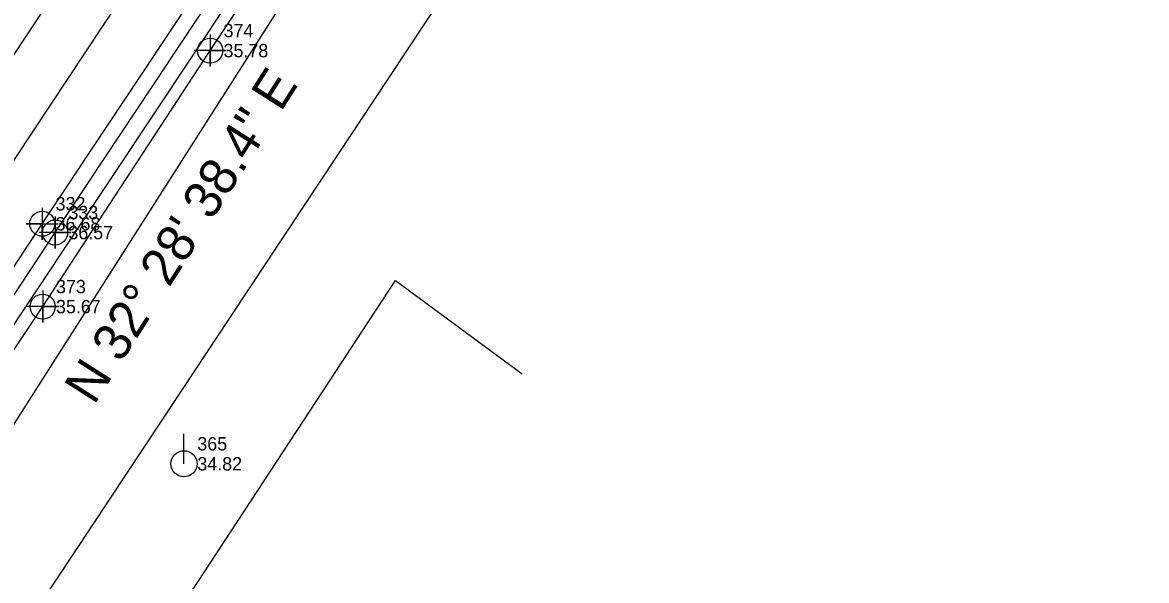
# Model space of a CAD drawing. Extents: x 2603627 to 2605187, y 896619 to 899063.
# Drawn here: x 2604872.4 to 2605082.8, y 898575.9 to 898680.4 of the extents above; entities that cross this region are included whole.
import ezdxf

# ---------------------------------------------------------------- set-up
doc = ezdxf.new("R2010")
doc.units = 0
for name, color, linetype in [('Exist Horizontal Alignment', 7, 'Continuous'), ('Exist Horizontal Baseline Alignment', 7, 'Continuous'), ('Exist Horizontal Baseline Alignment Direction Label', 7, 'Continuous'), ('Exist Right of Way Line', 7, 'Continuous'), ('Exist Roads EOP', 7, 'Continuous'), ('Exist Roads EOP Cogo Elevation', 7, 'Continuous'), ('Exist Roads EOP Cogo Number', 7, 'Continuous'), ('Exist Roads EOP Cogo Point CELL', 7, 'Continuous'), ('Exist Roads EOT', 7, 'Continuous'), ('Exist Roads EOT Cogo Elevation', 7, 'Continuous'), ('Exist Roads EOT Cogo Number', 7, 'Continuous'), ('Exist Roads EOT Cogo Point CELL', 7, 'Continuous'), ('Exist Utilities Power Pole CELL', 7, 'Continuous'), ('Exist Utilities Power Pole Cogo Elevation', 7, 'Continuous'), ('Exist Utilities Power Pole Cogo Number', 7, 'Continuous'), ('Exist Utilities Telephone UG Cable SUE LOS C', 7, 'Continuous'), ('Exist Utilities Water UG Line SUE LOS B', 7, 'Continuous'), ('Exist Utilities Water UG Line SUE LOS B Cogo Elevation', 7, 'Continuous'), ('Exist Utilities Water UG Line SUE LOS B Cogo Number', 7, 'Continuous'), ('Exist Utilities Water UG Line SUE LOS B Cogo Point CELL', 7, 'Continuous'), ('Exist Vegetation Woods Line', 7, 'Continuous')]:
    doc.layers.add(name, color=color, linetype=linetype)

# ---------------------------------------------------------------- blocks, each defined once
blk = doc.blocks.new('EXIST ROADS EOT COGO POINT')
at = {"layer": 'Exist Roads EOT Cogo Point CELL'}
blk.add_lwpolyline([(0, 0.06), (0, -0.06), (0, 0), (-0.06, 0), (0.06, 0)], dxfattribs=at)
blk.add_circle((0, 0), 0.0469, dxfattribs=at)
blk = doc.blocks.new('EXIST ROADS EOP COGO POINT')
at = {"layer": 'Exist Roads EOP Cogo Point CELL'}
blk.add_lwpolyline([(0, 0.06), (0, -0.06), (0, 0), (0.06, 0), (-0.06, 0)], dxfattribs=at)
blk.add_circle((0, 0), 0.0469, dxfattribs=at)
blk = doc.blocks.new('EXIST UTILITIES WATER UG LINE SUE LOS B COGO POINT')
at = {"layer": 'Exist Utilities Water UG Line SUE LOS B Cogo Point CELL'}
blk.add_lwpolyline([(0, 0.06), (0, -0.06), (0, 0), (0.06, 0), (-0.06, 0)], dxfattribs=at)
blk.add_circle((0, 0), 0.0469, dxfattribs=at)

msp = doc.modelspace()

# ---------------------------------------------------------------- linework, layer by layer
at = {"layer": 'Exist Horizontal Alignment'}
msp.add_line((2604681.44, 898368.79), (2605041.11, 898911.74), dxfattribs=at)
at = {"layer": 'Exist Horizontal Baseline Alignment'}
msp.add_line((2604793.6, 898483.9), (2605028.26, 898852.56), dxfattribs=at)
at = {"layer": 'Exist Right of Way Line'}
msp.add_line((2604723.13, 898341.18), (2605082.79, 898884.13), dxfattribs=at)
at = {"layer": 'Exist Roads EOP'}
msp.add_lwpolyline([(2604713.86, 898392.44), (2604740.28, 898432.25), (2604768.45, 898474.26), (2604797.27, 898517.92), (2604823.93, 898558.47), (2604851.31, 898599.84), (2604878.52, 898641.09), (2604906.84, 898683.65), (2604934.68, 898725.71), (2604962.63, 898767.92), (2604989.32, 898808.49), (2605016.42, 898849.59), (2605045.34, 898893.33), (2605052.55, 898904.16)], dxfattribs=at)
at = {"layer": 'Exist Roads EOT'}
for points in [[(2604580.65, 898235.67), (2604609.23, 898279.3), (2604636.66, 898320.72), (2604665.18, 898363.91), (2604693.37, 898406.36), (2604719.95, 898446.05), (2604748, 898488.34), (2604776.15, 898530.84), (2604803.5, 898572.3), (2604830.95, 898613.91), (2604857.58, 898654.47), (2604886.02, 898697.38), (2604913.86, 898739.33), (2604942.03, 898781.72), (2604969.06, 898822.38), (2604996.07, 898863.44), (2605024.73, 898906.73), (2605032, 898917.78)], [(2604598.04, 898223.4), (2604627.23, 898267.23), (2604654.64, 898308.57), (2604683.28, 898352.01), (2604711.27, 898394.14), (2604737.98, 898434.05), (2604766.04, 898475.94), (2604794.96, 898519.26), (2604821.61, 898559.82), (2604848.89, 898601.4), (2604876.12, 898642.73), (2604904.4, 898685.35), (2604932.33, 898727.23), (2604960.29, 898769.49), (2604987.32, 898810.19), (2605014.12, 898850.95), (2605043.08, 898894.89), (2605050.2, 898905.72)]]:
    msp.add_lwpolyline(points, dxfattribs=at)
at = {"layer": 'Exist Utilities Power Pole CELL'}
for q in [(2604902.65, 898603.41), (2604902.65, 898597.79)]:
    msp.add_line((2604902.65, 898597.79), q, dxfattribs=at)
msp.add_circle((2604902.65, 898597.79), 2.45, dxfattribs=at)
at = {"layer": 'Exist Utilities Telephone UG Cable SUE LOS C'}
msp.add_line((2604850.74, 898593.69), (2605031.63, 898865.69), dxfattribs=at)
at = {"layer": 'Exist Utilities Water UG Line SUE LOS B'}
msp.add_lwpolyline([(2604590.41, 898183.07), (2604608.13, 898210.78), (2604631.33, 898247.72), (2604631.98, 898248.77), (2604637.93, 898260.9), (2604650.01, 898281.75), (2604670.13, 898312.66), (2604706.14, 898370.49), (2604744.2, 898428.79), (2604775.85, 898478.14), (2604817.62, 898541.22), (2604844.76, 898580.18), (2604876.2, 898627.22), (2604907.55, 898675.15), (2604931.69, 898711.47), (2604963.51, 898758.63), (2604991.08, 898800.9), (2605022.23, 898847.26), (2605044.13, 898880.13), (2605057.71, 898900.74)], dxfattribs=at)
at = {"layer": 'Exist Vegetation Woods Line'}
msp.add_lwpolyline([(2604864.62, 898513.8), (2604942.25, 898632.13), (2604965.96, 898614.62)], dxfattribs=at)

# ---------------------------------------------------------------- block references
at = {"layer": 'Exist Roads EOP Cogo Point CELL', "xscale": 50, "yscale": 50}
msp.add_blockref('EXIST ROADS EOP COGO POINT', (2604878.52, 898641.09), dxfattribs=at)
at = {"layer": 'Exist Roads EOT Cogo Point CELL', "xscale": 50, "yscale": 50}
msp.add_blockref('EXIST ROADS EOT COGO POINT', (2604876.12, 898642.73), dxfattribs=at)
at = {"layer": 'Exist Utilities Water UG Line SUE LOS B Cogo Point CELL', "xscale": 50, "yscale": 50}
for p in [(2604907.55, 898675.15), (2604876.2, 898627.22)]:
    msp.add_blockref('EXIST UTILITIES WATER UG LINE SUE LOS B COGO POINT', p, dxfattribs=at)

# ---------------------------------------------------------------- texts
at = {"layer": 'Exist Horizontal Baseline Alignment Direction Label'}
msp.add_text('N 32%%d 28\' 38.4" E', height=7, rotation=57.5227, dxfattribs=at).set_placement((2604885.83, 898608.64))
at = {"layer": 'Exist Roads EOP Cogo Elevation'}
msp.add_text('36.57', height=2.5, dxfattribs=at).set_placement((2604881.02, 898639.84))
at = {"layer": 'Exist Roads EOP Cogo Number'}
msp.add_text('333', height=2.5, dxfattribs=at).set_placement((2604881.02, 898643.59))
at = {"layer": 'Exist Roads EOT Cogo Elevation'}
msp.add_text('36.68', height=2.5, dxfattribs=at).set_placement((2604878.62, 898641.48))
at = {"layer": 'Exist Roads EOT Cogo Number'}
msp.add_text('332', height=2.5, dxfattribs=at).set_placement((2604878.62, 898645.23))
at = {"layer": 'Exist Utilities Power Pole Cogo Elevation'}
msp.add_text('34.82', height=2.5, dxfattribs=at).set_placement((2604905.15, 898596.54))
at = {"layer": 'Exist Utilities Power Pole Cogo Number'}
msp.add_text('365', height=2.5, dxfattribs=at).set_placement((2604905.15, 898600.29))
at = {"layer": 'Exist Utilities Water UG Line SUE LOS B Cogo Elevation'}
for s, p in [('35.78', (2604910.05, 898673.9)), ('35.67', (2604878.7, 898625.97))]:
    msp.add_text(s, height=2.5, dxfattribs=at).set_placement(p)
at = {"layer": 'Exist Utilities Water UG Line SUE LOS B Cogo Number'}
for s, p in [('374', (2604910.05, 898677.65)), ('373', (2604878.7, 898629.72))]:
    msp.add_text(s, height=2.5, dxfattribs=at).set_placement(p)

doc.saveas('drawing.dxf')
